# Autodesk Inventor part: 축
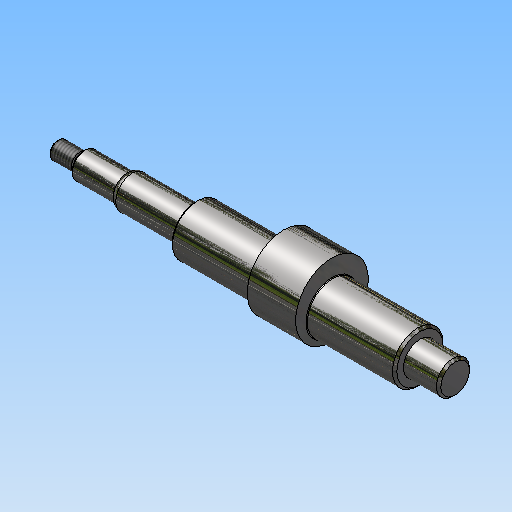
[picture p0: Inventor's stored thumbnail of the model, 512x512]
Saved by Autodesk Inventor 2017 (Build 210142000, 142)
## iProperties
Created: 2015-12
Part Number: 축
Document SubType Name: Modeling
Designer: mdu
Density: 7.86 g/cm^3
Material: 강철, 연강
Mass: 494.669 g
Surface Area: 129.298 cm^2
Volume: 62.935 cm^3
Appearance: 반광택
Author: mdu
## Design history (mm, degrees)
sketch "스케치1"
  geometry: L1 (62, 100.9)-(62, 67.1) reference; L2 (51, 101.2)-(51, 84) reference; L3 (-51, 84)-(-51, 101.2) reference; L4 (-62, 67.1)-(-62, 100.9) reference; L5 (-51.6, 91.5)-(-61.4, 91.5) reference; L6 (51.6, 91.5)-(61.4, 91.5) reference; L7 (67, 84)-(-114, 84); L8 (-77, 64.201)-(-77, 103.799) reference; L9 (67, 84)-(67, 91.5); L10 (67, 91.5)-(51, 91.5); L11 (51, 91.5)-(51, 95.5); L12 (51, 95.5)-(-51, 95.5); L13 (-51, 95.5)-(-51, 91.5); L14 (-51, 91.5)-(-82, 91.5); L15 (-82, 91.5)-(-82, 90); L16 (-82, 90)-(-102, 90); L17 (-102, 90)-(-102, 87); L18 (-103.5, 88)-(-114, 88); L19 (-114, 88)-(-114, 84); L20 (-102, 87)-(-103.5, 87); L21 (-103.5, 87)-(-103.5, 88); 2 further points
  constraints: 32 end point, 7 parallel, 6 point on line, 5 perpendicular, 2 collinear, 2 horizontal, 1 midpoint, 4 other
  dimensions: "d0" = 5 distance from line of L7.start L1; "d2" = 5 distance between parallel lines of L15 L8; "d3" = 23 diameter of L12 L7; "d4" = 12 diameter of L16 L7; "d5" = 1.5 distance of L17.end L20.end; "d6" = 6 diameter of L20 L7; "d7" = 20 distance of L15.end L16.end; "d8" = 12 distance between parallel lines of L17 L19; "d9" = 8 diameter of L18 L7
revolve "회전1" sketch "스케치1" stored, may be unused: angle "d10" = 90 deg
sketch "스케치2"
  geometry: C1 r 11.5 at (84, 0) reference; C2 r 11.5 at (84, 0) reference; C3 r 16.5 at (87, 0); 1 further point
  constraints: 1 centre point, 1 horizontal alignment
  dimensions: "d11" = 33 diameter of C3; "d12" = 3 distance of C3.centre C1.centre
extrude "돌출1" join sketch "스케치2" stored distance "d13" = 22; taper "d14" = 0 deg
chamfer "모따기1" distance "d15" = 1; stored, may be unused: second distance "d16" = 2, angle "d17" = 45 deg
feature "스레드1" dims "d18" = 10, "d19" = 0
node "작업 평면1"
sketch "스케치3"
  geometry: L1 (-5, -2)-(3, -2); L2 (3, 2)-(-5, 2); L3 (-10, -5)-(-10, 5) reference; A1 r 2 centre (3, 0) between (3, -2) and (3, 2); A2 r 2 centre (-5, 0) between (-5, 2) and (-5, -2); 2 further points
  constraints: 4 end point, 4 point on circle, 4 tangent, 2 centre point, 1 horizontal, 1 horizontal alignment, 1 midpoint, 1 parallel
  dimensions: "d20" = 4 distance between parallel lines of L1 L2; "d21" = 12 dimension on A1 A2; "d22" = 3 distance edge to line of A2 L3
extrude "돌출2" cut sketch "스케치3" distance "d23" = 2.5; taper "d24" = 0 deg
fillet "모깎기1" dims "d25" = 0.3
fillet "모깎기2" dims "d26" = 3
node "솔리드1"
node "참조1"
node "참조2"
node "참조3"
node "참조4"
node "참조5"
node "투영된 루프1"
